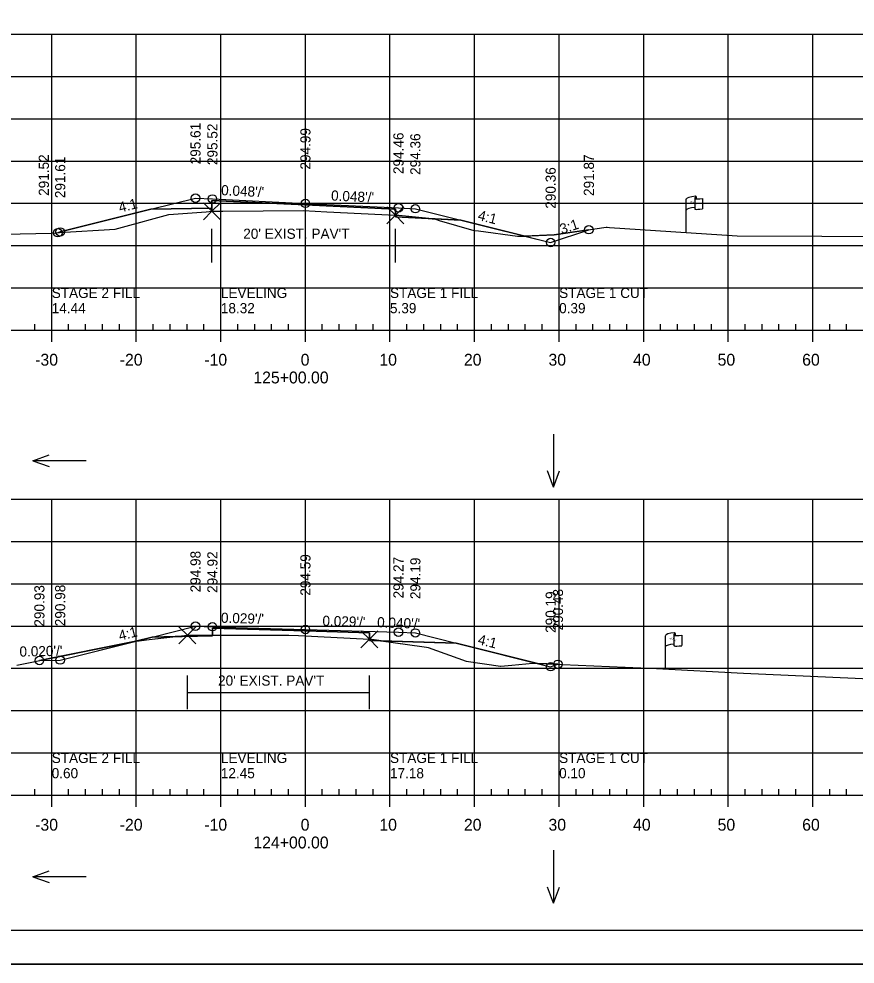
# Model space of a CAD drawing. Extents: x 1370843 to 1371177, y 380307 to 382654.
# Drawn here: x 1370979.8 to 1371078.7, y 382227.5 to 382339.3 of the extents above; entities that cross this region are included whole.
import ezdxf

# ---------------------------------------------------------------- set-up
doc = ezdxf.new("R2010")
doc.units = 0
for name, color, linetype in [('R_Alt Surface', 7, 'Continuous'), ('R_Axis', 7, 'Continuous'), ('R_Axis Annot', 7, 'Continuous'), ('R_Border', 7, 'Continuous'), ('R_Exist Surface', 7, 'Continuous'), ('R_Exist Surface Annot', 7, 'Continuous'), ('R_Fin Surface', 7, 'Continuous'), ('R_Fin Surface Annot', 7, 'Continuous'), ('R_Grid', 7, 'Continuous'), ('R_No Plot', 7, 'Continuous'), ('R_ROW', 7, 'Continuous'), ('R_Water Annot', 7, 'Continuous')]:
    doc.layers.add(name, color=color, linetype=linetype)

msp = doc.modelspace()

# ---------------------------------------------------------------- linework, layer by layer
at = {"layer": 'R_Alt Surface'}
for points in [[(1370995.42, 382316.78), (1371002.65, 382316.93), (1371002.65, 382317.84), (1371013.71, 382317.31), (1371024.35, 382316.8), (1371024.35, 382315.88), (1371032.08, 382315.51)], [(1370995.57, 382266.18), (1371002.71, 382266.32), (1371002.71, 382267.24), (1371013.71, 382266.92), (1371021.28, 382266.69), (1371021.28, 382265.78), (1371031.53, 382265.47)]]:
    msp.add_lwpolyline(points, dxfattribs=at)
at = {"layer": 'R_Axis'}
for p, q in [((1370981.71, 382302.49), (1370981.71, 382303.19)), ((1370985.71, 382302.49), (1370985.71, 382303.19)), ((1370987.71, 382302.49), (1370987.71, 382303.19)), ((1370989.71, 382302.49), (1370989.71, 382303.19)), ((1370991.71, 382302.49), (1370991.71, 382303.19)), ((1370995.71, 382302.49), (1370995.71, 382303.19)), ((1370997.71, 382302.49), (1370997.71, 382303.19)), ((1370999.71, 382302.49), (1370999.71, 382303.19)), ((1371001.71, 382302.49), (1371001.71, 382303.19)), ((1371005.71, 382302.49), (1371005.71, 382303.19)), ((1371007.71, 382302.49), (1371007.71, 382303.19)), ((1371009.71, 382302.49), (1371009.71, 382303.19)), ((1371011.71, 382302.49), (1371011.71, 382303.19)), ((1371015.71, 382302.49), (1371015.71, 382303.19)), ((1371017.71, 382302.49), (1371017.71, 382303.19)), ((1371019.71, 382302.49), (1371019.71, 382303.19)), ((1371021.71, 382302.49), (1371021.71, 382303.19)), ((1371025.71, 382302.49), (1371025.71, 382303.19)), ((1371027.71, 382302.49), (1371027.71, 382303.19)), ((1371029.71, 382302.49), (1371029.71, 382303.19)), ((1371031.71, 382302.49), (1371031.71, 382303.19)), ((1371035.71, 382302.49), (1371035.71, 382303.19)), ((1371037.71, 382302.49), (1371037.71, 382303.19)), ((1371039.71, 382302.49), (1371039.71, 382303.19)), ((1371041.71, 382302.49), (1371041.71, 382303.19)), ((1371045.71, 382302.49), (1371045.71, 382303.19)), ((1371047.71, 382302.49), (1371047.71, 382303.19)), ((1371049.71, 382302.49), (1371049.71, 382303.19)), ((1371051.71, 382302.49), (1371051.71, 382303.19)), ((1371055.71, 382302.49), (1371055.71, 382303.19)), ((1371057.71, 382302.49), (1371057.71, 382303.19)), ((1371059.71, 382302.49), (1371059.71, 382303.19)), ((1371061.71, 382302.49), (1371061.71, 382303.19)), ((1371065.71, 382302.49), (1371065.71, 382303.19)), ((1371067.71, 382302.49), (1371067.71, 382303.19)), ((1371069.71, 382302.49), (1371069.71, 382303.19)), ((1371071.71, 382302.49), (1371071.71, 382303.19)), ((1371075.71, 382302.49), (1371075.71, 382303.19)), ((1371077.71, 382302.49), (1371077.71, 382303.19)), ((1370868.71, 382302.49), (1371158.71, 382302.49)), ((1370983.71, 382301.09), (1370983.71, 382302.49)), ((1370993.71, 382301.09), (1370993.71, 382302.49)), ((1371003.71, 382301.09), (1371003.71, 382302.49)), ((1371013.71, 382301.09), (1371013.71, 382302.49)), ((1371023.71, 382301.09), (1371023.71, 382302.49)), ((1371033.71, 382301.09), (1371033.71, 382302.49)), ((1371043.71, 382301.09), (1371043.71, 382302.49)), ((1371053.71, 382301.09), (1371053.71, 382302.49)), ((1371063.71, 382301.09), (1371063.71, 382302.49)), ((1371073.71, 382301.09), (1371073.71, 382302.49)), ((1370868.71, 382247.49), (1371158.71, 382247.49)), ((1370981.71, 382247.49), (1370981.71, 382248.19)), ((1370983.71, 382246.09), (1370983.71, 382247.49)), ((1370985.71, 382247.49), (1370985.71, 382248.19)), ((1370987.71, 382247.49), (1370987.71, 382248.19)), ((1370989.71, 382247.49), (1370989.71, 382248.19)), ((1370991.71, 382247.49), (1370991.71, 382248.19)), ((1370993.71, 382246.09), (1370993.71, 382247.49)), ((1370995.71, 382247.49), (1370995.71, 382248.19)), ((1370997.71, 382247.49), (1370997.71, 382248.19)), ((1370999.71, 382247.49), (1370999.71, 382248.19)), ((1371001.71, 382247.49), (1371001.71, 382248.19)), ((1371003.71, 382246.09), (1371003.71, 382247.49)), ((1371005.71, 382247.49), (1371005.71, 382248.19)), ((1371007.71, 382247.49), (1371007.71, 382248.19)), ((1371009.71, 382247.49), (1371009.71, 382248.19)), ((1371011.71, 382247.49), (1371011.71, 382248.19)), ((1371013.71, 382246.09), (1371013.71, 382247.49)), ((1371015.71, 382247.49), (1371015.71, 382248.19)), ((1371017.71, 382247.49), (1371017.71, 382248.19)), ((1371019.71, 382247.49), (1371019.71, 382248.19)), ((1371021.71, 382247.49), (1371021.71, 382248.19)), ((1371023.71, 382246.09), (1371023.71, 382247.49)), ((1371025.71, 382247.49), (1371025.71, 382248.19)), ((1371027.71, 382247.49), (1371027.71, 382248.19)), ((1371029.71, 382247.49), (1371029.71, 382248.19)), ((1371031.71, 382247.49), (1371031.71, 382248.19)), ((1371033.71, 382246.09), (1371033.71, 382247.49)), ((1371035.71, 382247.49), (1371035.71, 382248.19)), ((1371037.71, 382247.49), (1371037.71, 382248.19)), ((1371039.71, 382247.49), (1371039.71, 382248.19)), ((1371041.71, 382247.49), (1371041.71, 382248.19)), ((1371043.71, 382246.09), (1371043.71, 382247.49)), ((1371045.71, 382247.49), (1371045.71, 382248.19)), ((1371047.71, 382247.49), (1371047.71, 382248.19)), ((1371049.71, 382247.49), (1371049.71, 382248.19)), ((1371051.71, 382247.49), (1371051.71, 382248.19)), ((1371053.71, 382246.09), (1371053.71, 382247.49)), ((1371055.71, 382247.49), (1371055.71, 382248.19)), ((1371057.71, 382247.49), (1371057.71, 382248.19)), ((1371059.71, 382247.49), (1371059.71, 382248.19)), ((1371061.71, 382247.49), (1371061.71, 382248.19)), ((1371063.71, 382246.09), (1371063.71, 382247.49)), ((1371065.71, 382247.49), (1371065.71, 382248.19)), ((1371067.71, 382247.49), (1371067.71, 382248.19)), ((1371069.71, 382247.49), (1371069.71, 382248.19)), ((1371071.71, 382247.49), (1371071.71, 382248.19)), ((1371073.71, 382246.09), (1371073.71, 382247.49)), ((1371075.71, 382247.49), (1371075.71, 382248.19)), ((1371077.71, 382247.49), (1371077.71, 382248.19))]:
    msp.add_line(p, q, dxfattribs=at)
at = {"layer": 'R_Border'}
msp.add_line((1371171.89, 382231.49), (1370855.71, 382231.49), dxfattribs=at)
at = {"layer": 'R_Exist Surface'}
for points in [[(1370974.44, 382313.75), (1370983.69, 382313.95), (1370984.64, 382314.03), (1370991.23, 382314.44), (1370992.09, 382314.66), (1370997.54, 382316.15), (1371001.98, 382316.49), (1371002.65, 382316.55), (1371003.95, 382316.56), (1371013.5, 382316.64), (1371016.25, 382316.5), (1371024.35, 382316.08), (1371028.06, 382315.72), (1371029.08, 382315.61), (1371029.54, 382315.47), (1371033.62, 382314.29), (1371034.16, 382314.22), (1371038.8, 382313.59), (1371039.44, 382313.6), (1371043.12, 382313.78), (1371049.27, 382314.65), (1371049.38, 382314.67), (1371049.68, 382314.64), (1371064.78, 382313.66), (1371074.77, 382313.62), (1371104.7, 382313.54)], [(1370979.57, 382262.87), (1370993.46, 382265.68), (1370995.22, 382265.88), (1370999.76, 382266.4), (1371001.09, 382266.41), (1371011.76, 382266.43), (1371012.89, 382266.37), (1371021.28, 382265.92), (1371027.77, 382265.04), (1371028.02, 382265.01), (1371028.21, 382264.95), (1371032.71, 382263.35), (1371036.77, 382262.74), (1371036.83, 382262.73), (1371038.11, 382262.85), (1371040.6, 382263.09), (1371042.26, 382263.02), (1371055.24, 382262.45), (1371065.53, 382261.92), (1371095.42, 382260.59), (1371096.13, 382260.66), (1371096.24, 382260.67), (1371098.72, 382260.91)]]:
    msp.add_lwpolyline(points, dxfattribs=at)
at = {"layer": 'R_Exist Surface Annot'}
for p, q in [((1371002.65, 382310.49), (1371002.65, 382314.49)), ((1371024.35, 382310.49), (1371024.35, 382314.49)), ((1371002.65, 382312.49), (1371024.35, 382312.49)), ((1370999.76, 382257.64), (1370999.76, 382261.64)), ((1371021.28, 382257.64), (1371021.28, 382261.64)), ((1370999.76, 382259.64), (1371021.28, 382259.64))]:
    msp.add_line(p, q, dxfattribs=at)
at = {"layer": 'R_Fin Surface'}
for points in [[(1370984.44, 382314.01), (1370984.71, 382314.1), (1370995.42, 382316.78), (1371000.71, 382318.1), (1371002.71, 382318.01), (1371013.71, 382317.48), (1371024.71, 382316.95), (1371026.71, 382316.85), (1371032.08, 382315.51), (1371042.71, 382312.85), (1371047.23, 382314.36)], [(1370982.25, 382263.42), (1370984.7, 382263.47), (1370984.71, 382263.47), (1370995.57, 382266.18), (1371000.71, 382267.47), (1371002.71, 382267.41), (1371013.71, 382267.08), (1371024.71, 382266.76), (1371026.71, 382266.68), (1371031.53, 382265.47), (1371042.71, 382262.68), (1371043.57, 382262.97)]]:
    msp.add_lwpolyline(points, dxfattribs=at)
at = {"layer": 'R_Grid'}
for p, q in [((1370868.71, 382337.49), (1371158.71, 382337.49)), ((1370983.71, 382302.49), (1370983.71, 382337.49)), ((1370993.71, 382302.49), (1370993.71, 382337.49)), ((1371003.71, 382302.49), (1371003.71, 382337.49)), ((1371013.71, 382302.49), (1371013.71, 382337.49)), ((1371023.71, 382302.49), (1371023.71, 382337.49)), ((1371033.71, 382302.49), (1371033.71, 382337.49)), ((1371043.71, 382302.49), (1371043.71, 382337.49)), ((1371053.71, 382302.49), (1371053.71, 382337.49)), ((1371063.71, 382302.49), (1371063.71, 382337.49)), ((1371073.71, 382302.49), (1371073.71, 382337.49)), ((1370868.71, 382332.49), (1371158.71, 382332.49)), ((1370868.71, 382327.49), (1371158.71, 382327.49)), ((1370868.71, 382322.49), (1371158.71, 382322.49)), ((1370868.71, 382317.49), (1371158.71, 382317.49)), ((1370868.71, 382312.49), (1371158.71, 382312.49)), ((1370868.71, 382307.49), (1371158.71, 382307.49)), ((1370868.71, 382302.49), (1371158.71, 382302.49)), ((1370868.71, 382282.49), (1371158.71, 382282.49)), ((1370983.71, 382247.49), (1370983.71, 382282.49)), ((1370993.71, 382247.49), (1370993.71, 382282.49)), ((1371003.71, 382247.49), (1371003.71, 382282.49)), ((1371013.71, 382247.49), (1371013.71, 382282.49)), ((1371023.71, 382247.49), (1371023.71, 382282.49)), ((1371033.71, 382247.49), (1371033.71, 382282.49)), ((1371043.71, 382247.49), (1371043.71, 382282.49)), ((1371053.71, 382247.49), (1371053.71, 382282.49)), ((1371063.71, 382247.49), (1371063.71, 382282.49)), ((1371073.71, 382247.49), (1371073.71, 382282.49)), ((1370868.71, 382277.49), (1371158.71, 382277.49)), ((1370868.71, 382272.49), (1371158.71, 382272.49)), ((1370868.71, 382267.49), (1371158.71, 382267.49)), ((1370868.71, 382262.49), (1371158.71, 382262.49)), ((1370868.71, 382257.49), (1371158.71, 382257.49)), ((1370868.71, 382252.49), (1371158.71, 382252.49)), ((1370868.71, 382247.49), (1371158.71, 382247.49))]:
    msp.add_line(p, q, dxfattribs=at)
at = {"layer": 'R_No Plot'}
for p, q in [((1371002.65, 382316.93), (1371002.65, 382316.55)), ((1371002.65, 382316.55), (1371002.65, 382316.93)), ((1370843.31, 382227.51), (1371176.64, 382227.51))]:
    msp.add_line(p, q, dxfattribs=at)
for points in [[(1370843.3, 382440.84), (1371176.64, 382440.84), (1371176.64, 382227.51), (1370843.3, 382227.51)], [(1371089.63, 382436.95), (1371089.63, 382427.07), (1371125.36, 382427.07), (1371125.36, 382424.15), (1371148.56, 382424.15), (1371148.56, 382399.82), (1371171.89, 382399.82), (1371171.89, 382231.49), (1370855.71, 382231.49), (1370855.71, 382436.95)], [(1371024.35, 382316.08), (1371024.35, 382315.88), (1371028.32, 382315.69)], [(1371028.32, 382315.69), (1371029.08, 382315.61), (1371029.54, 382315.47), (1371033.62, 382314.29), (1371034.16, 382314.22), (1371038.8, 382313.59), (1371039.44, 382313.6), (1371039.67, 382313.61), (1371032.08, 382315.51)], [(1371039.67, 382313.61), (1371042.71, 382312.85), (1371047.23, 382314.36), (1371043.12, 382313.78)], [(1370993.67, 382265.71), (1370995.22, 382265.88), (1370998.3, 382266.24), (1370995.57, 382266.18)], [(1371002.71, 382266.41), (1371002.71, 382266.32), (1370998.3, 382266.24), (1370999.76, 382266.4), (1371001.09, 382266.41)], [(1371002.71, 382266.41), (1371011.76, 382266.43), (1371012.89, 382266.37), (1371021.28, 382265.92), (1371021.28, 382266.69), (1371013.71, 382266.92), (1371002.71, 382267.24)], [(1370982.25, 382263.42), (1370984.7, 382263.47), (1370993.67, 382265.71), (1370993.46, 382265.68)], [(1371021.28, 382265.92), (1371021.28, 382265.78), (1371022.67, 382265.74)], [(1371022.67, 382265.74), (1371027.77, 382265.04), (1371028.02, 382265.01), (1371028.21, 382264.95), (1371032.71, 382263.35), (1371036.77, 382262.74), (1371036.83, 382262.73), (1371038.11, 382262.85), (1371040.6, 382263.09), (1371041.16, 382263.07), (1371031.53, 382265.47)], [(1371041.16, 382263.07), (1371042.71, 382262.68), (1371043.57, 382262.97), (1371042.26, 382263.02)]]:
    msp.add_lwpolyline(points, close=True, dxfattribs=at)
for points in [[(1371002.65, 382316.55), (1371003.95, 382316.56), (1371013.5, 382316.64), (1371016.25, 382316.5), (1371024.35, 382316.08), (1371024.35, 382316.8), (1371013.71, 382317.31), (1371002.65, 382317.84), (1371002.65, 382316.93)], [(1371002.65, 382316.93), (1370995.42, 382316.78), (1370984.71, 382314.1), (1370984.44, 382314.01), (1370984.64, 382314.03), (1370991.23, 382314.44), (1370992.09, 382314.66), (1370997.54, 382316.15), (1371001.98, 382316.49), (1371002.65, 382316.55)], [(1371002.65, 382316.55), (1371001.65, 382317.55), (1371002.65, 382316.55), (1371001.65, 382315.55), (1371002.65, 382316.55), (1371003.65, 382315.55), (1371002.65, 382316.55), (1371003.65, 382317.55)], [(1371024.35, 382316.08), (1371023.35, 382317.08), (1371024.35, 382316.08), (1371023.35, 382315.08), (1371024.35, 382316.08), (1371025.35, 382315.08), (1371024.35, 382316.08), (1371025.35, 382317.08)], [(1370999.76, 382266.4), (1370998.76, 382267.4), (1370999.76, 382266.4), (1370998.76, 382265.4), (1370999.76, 382266.4), (1371000.76, 382265.4), (1370999.76, 382266.4), (1371000.76, 382267.4)], [(1371021.28, 382265.92), (1371020.28, 382266.92), (1371021.28, 382265.92), (1371020.28, 382264.92), (1371021.28, 382265.92), (1371022.28, 382264.92), (1371021.28, 382265.92), (1371022.28, 382266.92)]]:
    msp.add_lwpolyline(points, dxfattribs=at)
for centre in [(1371000.71, 382318.1), (1371002.71, 382318.01), (1371013.71, 382317.48), (1371024.71, 382316.95), (1371026.71, 382316.85), (1370984.44, 382314.01), (1370984.71, 382314.1), (1371047.23, 382314.36), (1371042.71, 382312.85), (1371000.71, 382267.47), (1371002.71, 382267.41), (1371013.71, 382267.08), (1371024.71, 382266.76), (1371026.71, 382266.68), (1370984.71, 382263.47), (1370982.25, 382263.42), (1371042.71, 382262.68), (1371043.57, 382262.97)]:
    msp.add_circle(centre, 0.5, dxfattribs=at)
at = {"layer": 'R_ROW'}
for p, q in [((1371058.75, 382314.05), (1371058.75, 382318)), ((1371059.75, 382318.1), (1371059.75, 382318.08)), ((1371059.75, 382318.08), (1371059.75, 382316.86)), ((1371059.92, 382318.25), (1371059.92, 382318.01)), ((1371060.68, 382318.06), (1371060.68, 382316.82)), ((1371056.28, 382262.4), (1371056.28, 382266.35)), ((1371057.28, 382266.45), (1371057.28, 382266.43)), ((1371057.28, 382266.43), (1371057.28, 382265.21)), ((1371057.45, 382266.6), (1371057.45, 382266.36)), ((1371058.21, 382266.41), (1371058.21, 382265.17))]:
    msp.add_line(p, q, dxfattribs=at)
for centre, radius, start, end in [((1371059.83, 382318.1), 0.078, 88.6458, 274.2828), ((1371059.84, 382318.25), 0.0783, 263.0712, 93.9564), ((1371059.83, 382316.86), 0.0783, 180, 273.9564), ((1371057.36, 382266.45), 0.078, 88.6458, 274.2828), ((1371057.37, 382266.6), 0.0783, 263.0712, 93.9564), ((1371057.36, 382265.21), 0.0783, 180, 273.9564)]:
    msp.add_arc(centre, radius, start, end, dxfattribs=at)
for centre, major_axis, ratio, start_param, end_param in [((1371060.34, 382318.04), (-1.58, -0.04), 0.19887, 5.030368, 6.283185), ((1371061.04, 382318.16), (-1.23, -0.13), 0.052933, 0.159456, 1.268315), ((1371060.33, 382316.73), (-1.58, -0.04), 0.19887, 5.083035, 6.194897), ((1371061.04, 382316.92), (-1.23, -0.13), 0.052933, 0.159456, 1.268315), ((1371057.87, 382266.4), (-1.58, -0.04), 0.19887, 5.030368, 6.283185), ((1371058.57, 382266.51), (-1.23, -0.13), 0.052933, 0.159456, 1.268315), ((1371057.86, 382265.08), (-1.58, -0.04), 0.19887, 5.083035, 6.194897), ((1371058.57, 382265.27), (-1.23, -0.13), 0.052933, 0.159456, 1.268315)]:
    msp.add_ellipse(centre, major_axis=major_axis, ratio=ratio, start_param=start_param, end_param=end_param, dxfattribs=at)
at = {"layer": 'R_Water Annot'}
for p, q in [((1371043.05, 382290.2), (1371043.05, 382283.91)), ((1370981.48, 382287.05), (1370983.41, 382287.75)), ((1370987.77, 382287.05), (1370981.48, 382287.05)), ((1370981.48, 382287.05), (1370983.41, 382286.35)), ((1371043.05, 382283.91), (1371042.35, 382285.83)), ((1371043.05, 382283.91), (1371043.75, 382285.83)), ((1371043.05, 382240.98), (1371043.05, 382234.7)), ((1370981.48, 382237.84), (1370983.41, 382238.54)), ((1370987.77, 382237.84), (1370981.48, 382237.84)), ((1370981.48, 382237.84), (1370983.41, 382237.14)), ((1371043.05, 382234.7), (1371042.35, 382236.62)), ((1371043.05, 382234.7), (1371043.75, 382236.62))]:
    msp.add_line(p, q, dxfattribs=at)

# ---------------------------------------------------------------- texts
at = {"layer": 'R_Axis Annot'}
for s, p in [('-30', (1370981.75, 382298.29)), ('-20', (1370991.75, 382298.29)), ('-10', (1371001.75, 382298.29)), ('0', (1371013.15, 382298.29)), ('10', (1371022.45, 382298.29)), ('20', (1371032.45, 382298.29)), ('30', (1371042.45, 382298.29)), ('40', (1371052.45, 382298.29)), ('50', (1371062.45, 382298.29)), ('60', (1371072.45, 382298.29)), ('125+00.00', (1371007.55, 382296.19)), ('-30', (1370981.75, 382243.29)), ('-20', (1370991.75, 382243.29)), ('-10', (1371001.75, 382243.29)), ('0', (1371013.15, 382243.29)), ('10', (1371022.45, 382243.29)), ('20', (1371032.45, 382243.29)), ('30', (1371042.45, 382243.29)), ('40', (1371052.45, 382243.29)), ('50', (1371062.45, 382243.29)), ('60', (1371072.45, 382243.29)), ('124+00.00', (1371007.55, 382241.19))]:
    msp.add_text(s, height=1.4, dxfattribs=at).set_placement(p)
at = {"layer": 'R_Exist Surface Annot'}
for p in [(1371006.36, 382313.29), (1371003.38, 382260.44)]:
    msp.add_text("20' EXIST. PAV'T", height=1.2, dxfattribs=at).set_placement(p)
at = {"layer": 'R_Fin Surface Annot'}
for s, rotation, p in [('295.61', 90, (1371001.31, 382322.1)), ('295.52', 90, (1371003.31, 382322.01)), ('294.99', 90, (1371014.31, 382321.48)), ('294.46', 90, (1371025.31, 382320.95)), ('294.36', 90, (1371027.31, 382320.85)), ('291.52', 90, (1370983.38, 382318.37)), ('291.87', 90, (1371047.83, 382318.36)), ('291.61', 90, (1370985.31, 382318.1)), ('290.36', 90, (1371043.31, 382316.85)), ("0.048'/'", 357.2519, (1371003.72, 382318.46)), ("0.048'/'", 357.2519, (1371016.72, 382317.83)), ('4:1', 14.0362, (1370991.78, 382316.39)), ('4:1', 345.9638, (1371034.02, 382315.54)), ('3:1', 18.4349, (1371044.02, 382313.82)), ('294.98', 90, (1371001.31, 382271.47)), ('294.92', 90, (1371003.31, 382271.41)), ('294.59', 90, (1371014.31, 382271.08)), ('294.27', 90, (1371025.31, 382270.76)), ('294.19', 90, (1371027.31, 382270.68)), ('290.93', 90, (1370982.85, 382267.42)), ('290.98', 90, (1370985.31, 382267.47)), ('290.48', 90, (1371044.17, 382266.97)), ('290.19', 90, (1371043.31, 382266.68)), ("0.029'/'", 358.3115, (1371003.71, 382267.88)), ("0.029'/'", 358.3115, (1371015.71, 382267.52)), ("0.040'/'", 357.7094, (1371022.17, 382267.36)), ('4:1', 14.0362, (1370991.78, 382265.75)), ('4:1', 345.9638, (1371034.02, 382265.37)), ("0.020'/'", 1.1458, (1370979.91, 382263.87))]:
    msp.add_text(s, height=1.2, rotation=rotation, dxfattribs=at).set_placement(p)
at = {"layer": 'R_No Plot'}
for s, p in [('STAGE 2 FILL', (1370983.71, 382306.29)), ('LEVELING', (1371003.71, 382306.29)), ('STAGE 1 FILL', (1371023.71, 382306.29)), ('STAGE 1 CUT', (1371043.71, 382306.29)), ('14.44', (1370983.71, 382304.49)), ('18.32', (1371003.71, 382304.49)), ('5.39', (1371023.71, 382304.49)), ('0.39', (1371043.71, 382304.49)), ('STAGE 2 FILL', (1370983.71, 382251.29)), ('LEVELING', (1371003.71, 382251.29)), ('STAGE 1 FILL', (1371023.71, 382251.29)), ('STAGE 1 CUT', (1371043.71, 382251.29)), ('0.60', (1370983.71, 382249.49)), ('12.45', (1371003.71, 382249.49)), ('17.18', (1371023.71, 382249.49)), ('0.10', (1371043.71, 382249.49))]:
    msp.add_text(s, height=1.2, dxfattribs=at).set_placement(p)
at = {"layer": 'R_ROW'}
for s, height, rotation, p in [('R ', 0.2, 9.9884, (1371059.27, 382317.5)), (' O', 0.2, 9.9884, (1371059.42, 382317.55)), ('DWB 11-9-07', 0.001, 90, (1371059.92, 382318.01)), ('W', 0.2, 351.1788, (1371059.75, 382317.38)), ('DWB 11-9-07', 0.001, 5.0717, (1371060.67, 382316.82)), ('DWB 11-9-07', 0.001, 90, (1371058.75, 382314.05)), ('DWB 11-9-07', 0.001, 90, (1371057.45, 382266.36)), ('R ', 0.2, 9.9884, (1371056.8, 382265.85)), (' O', 0.2, 9.9884, (1371056.95, 382265.9)), ('W', 0.2, 351.1788, (1371057.28, 382265.73)), ('DWB 11-9-07', 0.001, 5.0717, (1371058.2, 382265.17)), ('DWB 11-9-07', 0.001, 90, (1371056.28, 382262.4))]:
    msp.add_text(s, height=height, rotation=rotation, dxfattribs=at).set_placement(p)

doc.saveas('drawing.dxf')
